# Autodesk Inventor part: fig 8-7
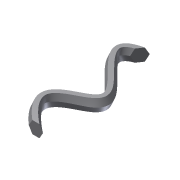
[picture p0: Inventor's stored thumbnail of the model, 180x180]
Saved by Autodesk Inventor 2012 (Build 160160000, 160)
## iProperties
Created: 2006-01
Part Number: fig 8-7
Document SubType Name: Modeling
Designer: CADCIM
Density: 1 g/cm^3
Material: Default
Author: CADCIM
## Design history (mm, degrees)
sketch "Sketch1"
  geometry: 5 further points
  constraints: 5 other
sketch "Sketch2"
  geometry: L1 (-4.728, 0)-(-2.364, 4.094); L2 (-2.364, 4.094)-(2.364, 4.094); L3 (2.364, 4.094)-(4.728, 0); L4 (4.728, 0)-(2.364, -4.094); L5 (2.364, -4.094)-(-2.364, -4.094); L6 (-2.364, -4.094)-(-4.728, 0); 1 further point
  constraints: 12 end point, 13 other
sweep "Sweep4" sketch "Sketch1", "Sketch2" dims "d3" = 0
body "Solid2"
